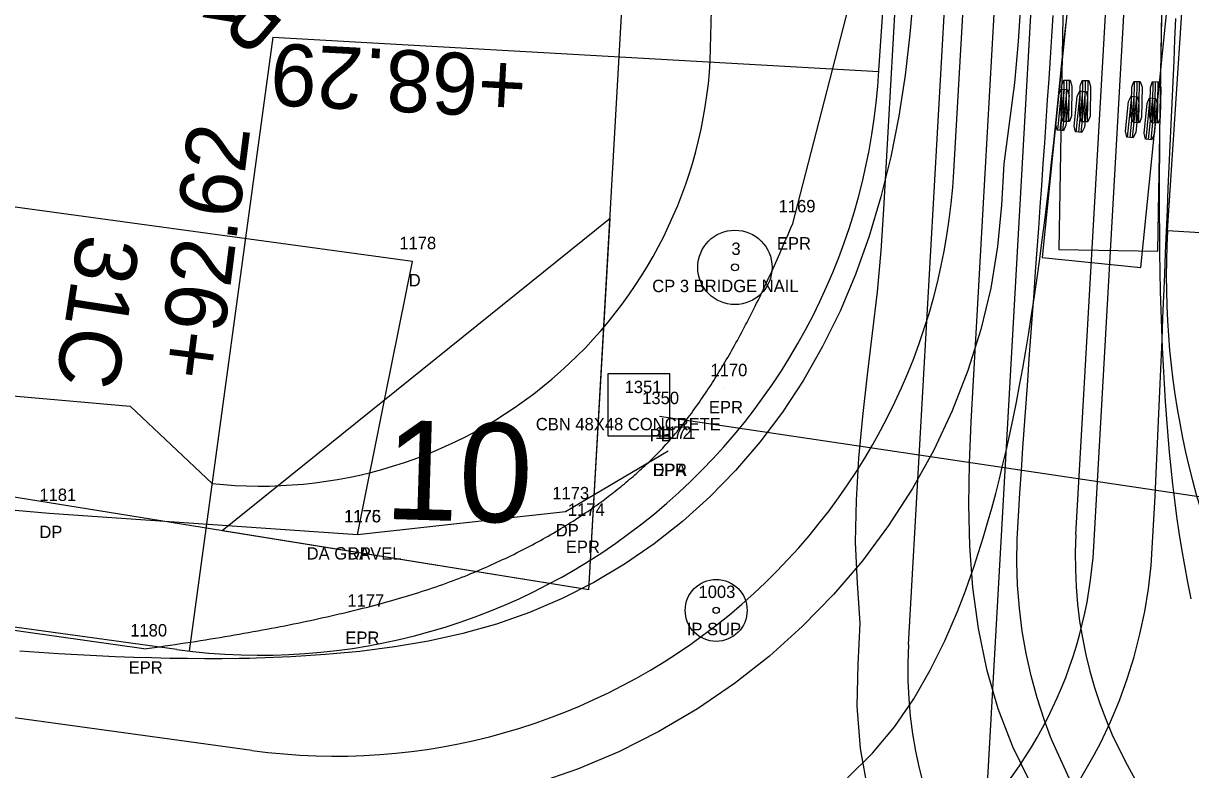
# Model space of a CAD drawing. Extents: x 1812113 to 1819860, y 1177290 to 1181185.
# Drawn here: x 1813586.4 to 1813680.6, y 1178765.6 to 1178825.8 of the extents above; entities that cross this region are included whole.
import ezdxf

# ---------------------------------------------------------------- set-up
doc = ezdxf.new("R2010")
doc.units = 0
for name, color, linetype in [('RD_EX_DR_Inlet', 7, 'Continuous'), ('RD_EX_DR_Inlet_txCode', 7, 'Continuous'), ('RD_EX_DR_Pipe', 7, 'Continuous'), ('RD_EX_DR_Pipe_txCode', 7, 'Continuous'), ('RD_EX_Driveway', 7, 'Continuous'), ('RD_EX_Driveway_txCode', 7, 'Continuous'), ('RD_EX_DV_Prop_txCode', 7, 'Continuous'), ('RD_EX_DV_PropPin', 7, 'Continuous'), ('RD_EX_Road', 7, 'Continuous'), ('RD_EX_Road_txCode', 7, 'Continuous'), ('RD_EX_RW', 7, 'Continuous'), ('RD_HC_CL', 7, 'Continuous'), ('RD_HC_Data', 7, 'Continuous'), ('RD_HC_TX_StaOther', 7, 'Continuous'), ('RD_HC_txCode', 7, 'Continuous'), ('RD_PD_ALT1_TrvlWay', 7, 'Continuous'), ('RD_PD_ALT3_TnTmp', 7, 'Continuous'), ('RD_PD_CstnLmt', 7, 'Continuous'), ('RD_PD_Final_TnTmp', 7, 'Continuous'), ('RD_PD_RW', 7, 'Continuous'), ('RD_Sketch5', 7, 'Continuous'), ('RD_Sketch7', 7, 'Continuous'), ('RD_Sketch8', 7, 'Continuous'), ('RD_Sketch9', 7, 'Continuous'), ('RD_SMD_Locator', 7, 'Continuous')]:
    doc.layers.add(name, color=color, linetype=linetype)

msp = doc.modelspace()

# ---------------------------------------------------------------- linework, layer by layer
at = {"layer": 'RD_EX_DR_Inlet'}
msp.add_line((1813638.558, 1178792.486), (1813638.558, 1178797.486), dxfattribs=at)
msp.add_lwpolyline([(1813638.558, 1178792.486), (1813638.558, 1178797.486), (1813633.558, 1178797.486), (1813633.558, 1178792.486)], close=True, dxfattribs=at)
at = {"layer": 'RD_EX_DR_Pipe'}
msp.add_line((1813690.767, 1178786.154), (1813637.713, 1178794.056), dxfattribs=at)
at = {"layer": 'RD_EX_Driveway'}
for points in [[(1813615.604, 1178795.765), (1813617.78, 1178806.553), (1813543.166, 1178816.742), (1813525.312, 1178791.789)], [(1813613.335, 1178784.516), (1813615.604, 1178795.765)], [(1813638.425, 1178791.252), (1813630.129, 1178786.377), (1813613.335, 1178784.516), (1813588.431, 1178786.243), (1813525.312, 1178791.789), (1813522.622, 1178785.744)]]:
    msp.add_lwpolyline(points, dxfattribs=at)
at = {"layer": 'RD_EX_DV_PropPin'}
for radius in [2.499, 0.25]:
    msp.add_circle((1813642.298, 1178778.414), radius, dxfattribs=at)
at = {"layer": 'RD_EX_Road'}
for p, q in [((1813653.668, 1178829.816), (1813648.43, 1178809.526)), ((1813596.091, 1178775.309), (1813522.622, 1178785.744))]:
    msp.add_line(p, q, dxfattribs=at)
msp.add_open_spline([(1813596.091, 1178775.309), (1813613.586, 1178777.713), (1813631.387, 1178785.043), (1813642.941, 1178796.308), (1813648.43, 1178809.526)], degree=2, dxfattribs=at)
at = {"layer": 'RD_EX_RW'}
for q in [(1813647.583, 1179054.502), (1813400.468, 1178817.382)]:
    msp.add_line((1813632.03, 1178780.068), q, dxfattribs=at)
at = {"layer": 'RD_HC_CL'}
msp.add_line((1813663.556, 1178753.116), (1813680.53, 1179052.635), dxfattribs=at)
at = {"layer": 'RD_HC_Data'}
for radius in [3, 0.282]:
    msp.add_circle((1813643.813, 1178806.089), radius, dxfattribs=at)
at = {"layer": 'RD_PD_ALT1_TrvlWay'}
for p, q in [((1813655.439, 1178821.971), (1813662.128, 1178921.747)), ((1813678.744, 1178809.043), (1813685.223, 1178908.833)), ((1813598.749, 1178775.26), (1813539.844, 1178783.309))]:
    msp.add_line(p, q, dxfattribs=at)
for centre, radius, start, end in [((1813605.519, 1178824.8), 50, 262.2191, 356.75649), ((1813743.64, 1178805.365), 65, 176.75649, 243.60449)]:
    msp.add_arc(centre, radius, start, end, dxfattribs=at)
at = {"layer": 'RD_PD_CstnLmt'}
for p, q in [((1813641.818, 1178822.743), (1813642.544, 1178854.467)), ((1813545.131, 1178799.286), (1813594.994, 1178794.879)), ((1813594.994, 1178794.879), (1813601.592, 1178788.655))]:
    msp.add_line(p, q, dxfattribs=at)
msp.add_arc((1813605.519, 1178824.8), 36.358, 263.80014, 356.75649, dxfattribs=at)
at = {"layer": 'RD_PD_Final_TnTmp'}
for p, q in [((1813606.513, 1178824.664), (1813599.745, 1178775.134)), ((1813606.513, 1178824.664), (1813655.433, 1178821.892)), ((1813740.735, 1178805.018), (1813678.744, 1178809.043))]:
    msp.add_line(p, q, dxfattribs=at)
at = {"layer": 'RD_PD_RW'}
for p, q in [((1813633.728, 1178810.02), (1813602.412, 1178784.841)), ((1813632.03, 1178780.068), (1813633.728, 1178810.02)), ((1813632.03, 1178780.068), (1813602.412, 1178784.841))]:
    msp.add_line(p, q, dxfattribs=at)
at = {"layer": 'RD_Sketch5'}
for p, q in [((1813672.244, 1178842.513), (1813668.622, 1178806.897)), ((1813676.581, 1178806.088), (1813680.203, 1178841.704)), ((1813672.794, 1178783.581), (1813675.97, 1178839.621)), ((1813669.875, 1178817.156), (1813670.212, 1178820.472)), ((1813670.082, 1178817.135), (1813670.419, 1178820.451)), ((1813670.289, 1178817.114), (1813670.627, 1178820.43)), ((1813671.367, 1178817.004), (1813671.704, 1178820.32)), ((1813671.574, 1178816.983), (1813671.912, 1178820.299)), ((1813671.782, 1178816.962), (1813672.119, 1178820.278)), ((1813675.512, 1178816.583), (1813675.85, 1178819.899)), ((1813675.72, 1178816.562), (1813676.057, 1178819.878)), ((1813675.927, 1178816.541), (1813676.264, 1178819.857)), ((1813677.005, 1178816.431), (1813677.342, 1178819.747)), ((1813677.212, 1178816.41), (1813677.549, 1178819.726)), ((1813677.419, 1178816.389), (1813677.756, 1178819.705)), ((1813668.622, 1178806.897), (1813676.581, 1178806.088))]:
    msp.add_line(p, q, dxfattribs=at)
for points in [[(1813662.421, 1178779.989), (1813662.682, 1178780.703), (1813663.098, 1178781.895), (1813663.491, 1178783.086), (1813663.863, 1178784.277), (1813664.215, 1178785.467), (1813664.549, 1178786.655), (1813664.867, 1178787.842), (1813665.169, 1178789.027), (1813665.456, 1178790.211), (1813665.731, 1178791.397), (1813666.003, 1178792.625), (1813666.272, 1178793.899), (1813666.536, 1178795.214), (1813666.796, 1178796.566), (1813667.05, 1178797.95), (1813667.297, 1178799.365), (1813667.537, 1178800.805), (1813667.77, 1178802.269), (1813667.995, 1178803.754), (1813668.214, 1178805.257), (1813668.425, 1178806.778), (1813668.63, 1178808.312), (1813668.828, 1178809.861), (1813669.019, 1178811.42), (1813669.204, 1178812.991), (1813669.383, 1178814.571), (1813669.557, 1178816.159), (1813669.725, 1178817.755), (1813669.889, 1178819.357), (1813670.053, 1178820.965), (1813670.217, 1178822.578), (1813670.381, 1178824.196), (1813670.546, 1178825.817)], [(1813672.832, 1178766.756), (1813673.347, 1178767.745), (1813674.143, 1178769.427), (1813674.859, 1178771.146), (1813675.495, 1178772.899), (1813676.048, 1178774.682), (1813676.517, 1178776.49), (1813676.901, 1178778.32), (1813677.198, 1178780.168), (1813677.408, 1178782.029), (1813677.536, 1178783.898), (1813677.641, 1178785.76), (1813677.738, 1178787.609), (1813677.829, 1178789.446), (1813677.914, 1178791.271), (1813677.995, 1178793.085), (1813678.073, 1178794.889), (1813678.149, 1178796.683), (1813678.223, 1178798.467), (1813678.296, 1178800.242), (1813678.368, 1178802.009), (1813678.44, 1178803.769), (1813678.512, 1178805.522), (1813678.584, 1178807.268), (1813678.657, 1178809.007), (1813678.73, 1178810.742), (1813678.804, 1178812.471), (1813678.879, 1178814.195), (1813678.954, 1178815.915), (1813679.031, 1178817.631), (1813679.108, 1178819.343), (1813679.186, 1178821.052), (1813679.265, 1178822.757), (1813679.345, 1178824.46), (1813679.426, 1178826.16)], [(1813652.907, 1178764.912), (1813654.933, 1178766.905), (1813656.713, 1178769.038), (1813658.25, 1178771.284), (1813659.584, 1178773.598), (1813660.749, 1178775.95), (1813661.774, 1178778.322), (1813662.421, 1178779.989)], [(1813671.527, 1178764.509), (1813672.832, 1178766.756)]]:
    msp.add_lwpolyline(points, dxfattribs=at)
for points in [[(1813670.341, 1178817.109), (1813669.823, 1178817.161), (1813669.715, 1178817.641), (1813669.958, 1178820.029), (1813670.161, 1178820.477), (1813670.678, 1178820.425), (1813670.787, 1178819.945), (1813670.544, 1178817.557)], [(1813671.833, 1178816.957), (1813671.316, 1178817.009), (1813671.207, 1178817.49), (1813671.45, 1178819.877), (1813671.653, 1178820.326), (1813672.17, 1178820.273), (1813672.279, 1178819.793), (1813672.036, 1178817.405)], [(1813675.978, 1178816.535), (1813675.461, 1178816.588), (1813675.352, 1178817.068), (1813675.595, 1178819.456), (1813675.798, 1178819.904), (1813676.316, 1178819.852), (1813676.424, 1178819.372), (1813676.181, 1178816.984)], [(1813677.471, 1178816.384), (1813676.953, 1178816.436), (1813676.845, 1178816.916), (1813677.087, 1178819.304), (1813677.291, 1178819.753), (1813677.808, 1178819.7), (1813677.917, 1178819.22), (1813677.674, 1178816.832)]]:
    msp.add_lwpolyline(points, close=True, dxfattribs=at)
msp.add_arc((1813637.85, 1178785.561), 35, 262.2191, 356.75649, dxfattribs=at)
at = {"layer": 'RD_Sketch7'}
for p, q in [((1813670.575, 1178843.323), (1813669.969, 1178807.528)), ((1813677.968, 1178807.393), (1813678.574, 1178843.188)), ((1813671.346, 1178784.53), (1813674.532, 1178840.756)), ((1813670.352, 1178817.857), (1813670.409, 1178821.189)), ((1813670.56, 1178817.853), (1813670.617, 1178821.186)), ((1813670.769, 1178817.85), (1813670.825, 1178821.182)), ((1813671.852, 1178817.831), (1813671.908, 1178821.164)), ((1813672.06, 1178817.828), (1813672.117, 1178821.161)), ((1813672.268, 1178817.824), (1813672.325, 1178821.157)), ((1813676.018, 1178817.761), (1813676.074, 1178821.094)), ((1813676.226, 1178817.757), (1813676.283, 1178821.09)), ((1813676.435, 1178817.754), (1813676.491, 1178821.086)), ((1813677.518, 1178817.735), (1813677.574, 1178821.068)), ((1813677.726, 1178817.732), (1813677.782, 1178821.065)), ((1813677.934, 1178817.728), (1813677.991, 1178821.061)), ((1813669.969, 1178807.528), (1813677.968, 1178807.393))]:
    msp.add_line(p, q, dxfattribs=at)
for points in [[(1813680.661, 1178779.355), (1813680.381, 1178780.702), (1813680.127, 1178782.04), (1813679.896, 1178783.37), (1813679.687, 1178784.691), (1813679.498, 1178786.003), (1813679.326, 1178787.307), (1813679.17, 1178788.603), (1813679.03, 1178789.891), (1813678.903, 1178791.18), (1813678.785, 1178792.506), (1813678.675, 1178793.87), (1813678.576, 1178795.268), (1813678.486, 1178796.696), (1813678.407, 1178798.15), (1813678.337, 1178799.628), (1813678.277, 1178801.128), (1813678.226, 1178802.645), (1813678.185, 1178804.179), (1813678.152, 1178805.728), (1813678.128, 1178807.29), (1813678.111, 1178808.863), (1813678.102, 1178810.446), (1813678.1, 1178812.039), (1813678.105, 1178813.639), (1813678.116, 1178815.247), (1813678.133, 1178816.861), (1813678.156, 1178818.481), (1813678.183, 1178820.106), (1813678.211, 1178821.736), (1813678.238, 1178823.37), (1813678.266, 1178825.007), (1813678.294, 1178826.648)], [(1813669.281, 1178768.228), (1813668.772, 1178769.603), (1813668.207, 1178771.351), (1813667.723, 1178773.128), (1813667.323, 1178774.93), (1813667.007, 1178776.753), (1813666.777, 1178778.592), (1813666.633, 1178780.444), (1813666.576, 1178782.303), (1813666.607, 1178784.166), (1813666.711, 1178786.025), (1813666.827, 1178787.872), (1813666.948, 1178789.705), (1813667.072, 1178791.527), (1813667.198, 1178793.338), (1813667.325, 1178795.138), (1813667.453, 1178796.929), (1813667.582, 1178798.71), (1813667.71, 1178800.483), (1813667.838, 1178802.248), (1813667.966, 1178804.005), (1813668.092, 1178805.756), (1813668.217, 1178807.501), (1813668.341, 1178809.24), (1813668.464, 1178810.973), (1813668.585, 1178812.702), (1813668.706, 1178814.427), (1813668.824, 1178816.147), (1813668.942, 1178817.864), (1813669.058, 1178819.577), (1813669.173, 1178821.287), (1813669.287, 1178822.994), (1813669.399, 1178824.699), (1813669.511, 1178826.401)], [(1813670.936, 1178764.574), (1813669.416, 1178767.888), (1813669.281, 1178768.228)]]:
    msp.add_lwpolyline(points, dxfattribs=at)
for points in [[(1813670.82, 1178817.849), (1813670.3, 1178817.857), (1813670.152, 1178818.327), (1813670.192, 1178820.726), (1813670.357, 1178821.19), (1813670.877, 1178821.182), (1813671.026, 1178820.712), (1813670.985, 1178818.313)], [(1813672.32, 1178817.823), (1813671.8, 1178817.832), (1813671.651, 1178818.301), (1813671.692, 1178820.701), (1813671.857, 1178821.165), (1813672.377, 1178821.156), (1813672.525, 1178820.687), (1813672.485, 1178818.287)], [(1813676.486, 1178817.753), (1813675.966, 1178817.762), (1813675.818, 1178818.231), (1813675.858, 1178820.63), (1813676.023, 1178821.094), (1813676.543, 1178821.086), (1813676.691, 1178820.616), (1813676.651, 1178818.217)], [(1813677.986, 1178817.727), (1813677.466, 1178817.736), (1813677.317, 1178818.205), (1813677.358, 1178820.605), (1813677.523, 1178821.069), (1813678.042, 1178821.06), (1813678.191, 1178820.591), (1813678.151, 1178818.191)]]:
    msp.add_lwpolyline(points, close=True, dxfattribs=at)
msp.add_arc((1813706.29, 1178782.549), 35, 176.75649, 248.72202, dxfattribs=at)
at = {"layer": 'RD_Sketch8'}
msp.add_line((1813657.822, 1178775.655), (1813662.021, 1178849.759), dxfattribs=at)
for points in [[(1813656.751, 1178827.461), (1813656.562, 1178824.123), (1813656.373, 1178820.785), (1813656.184, 1178817.447), (1813655.995, 1178814.109), (1813655.806, 1178810.771), (1813655.596, 1178807.434), (1813655.292, 1178804.102), (1813654.904, 1178800.769), (1813654.494, 1178797.425), (1813654.113, 1178794.065), (1813653.803, 1178790.685), (1813653.599, 1178787.295), (1813653.528, 1178783.917), (1813653.679, 1178780.611), (1813653.9, 1178777.386), (1813653.725, 1178774.053), (1813653.648, 1178770.684), (1813653.917, 1178767.267), (1813654.533, 1178763.843)], [(1813664.739, 1178827.009), (1813664.549, 1178823.671), (1813664.36, 1178820.333), (1813664.171, 1178816.995), (1813663.982, 1178813.657), (1813663.793, 1178810.319), (1813663.604, 1178806.981), (1813663.414, 1178803.643), (1813663.225, 1178800.305), (1813663.036, 1178796.967), (1813662.854, 1178793.628), (1813662.718, 1178790.288), (1813662.671, 1178786.945), (1813662.753, 1178783.603), (1813663.001, 1178780.27), (1813663.448, 1178776.959), (1813664.123, 1178773.687), (1813665.048, 1178770.49), (1813666.214, 1178767.448), (1813667.612, 1178764.595)]]:
    msp.add_lwpolyline(points, dxfattribs=at)
msp.add_arc((1813692.766, 1178773.675), 35, 176.75649, 250.88672, dxfattribs=at)
at = {"layer": 'RD_Sketch9'}
for p, q in [((1813661.488, 1178813.827), (1813662.81, 1178837.155)), ((1813604.798, 1178767.116), (1813538.862, 1178776.126))]:
    msp.add_line(p, q, dxfattribs=at)
for points in [[(1813658.241, 1178828.224), (1813657.939, 1178824.9), (1813657.545, 1178821.585), (1813657.037, 1178818.287), (1813656.397, 1178815.012), (1813655.607, 1178811.77), (1813654.66, 1178808.592), (1813653.558, 1178805.514), (1813652.302, 1178802.548), (1813650.896, 1178799.705), (1813649.342, 1178796.992), (1813647.646, 1178794.416), (1813645.815, 1178791.983), (1813643.856, 1178789.698), (1813641.776, 1178787.566), (1813639.583, 1178785.592), (1813637.285, 1178783.781), (1813634.892, 1178782.137), (1813632.413, 1178780.664), (1813629.857, 1178779.365), (1813627.235, 1178778.244), (1813624.557, 1178777.303), (1813621.835, 1178776.541), (1813619.083, 1178775.937), (1813616.313, 1178775.466), (1813613.534, 1178775.108), (1813610.751, 1178774.847), (1813607.966, 1178774.668), (1813605.183, 1178774.561), (1813604.626, 1178774.547)], [(1813666.885, 1178827.677), (1813666.688, 1178824.319), (1813666.398, 1178820.98), (1813665.95, 1178817.698), (1813665.529, 1178814.437), (1813665.34, 1178811.105), (1813665.026, 1178807.76), (1813664.466, 1178804.408), (1813663.665, 1178801.071), (1813662.627, 1178797.769), (1813661.358, 1178794.519), (1813659.863, 1178791.343), (1813658.15, 1178788.256), (1813656.226, 1178785.276), (1813654.1, 1178782.418), (1813651.78, 1178779.699), (1813649.278, 1178777.132), (1813646.604, 1178774.73), (1813643.77, 1178772.506), (1813640.79, 1178770.471), (1813637.676, 1178768.636), (1813634.442, 1178767.009), (1813631.103, 1178765.599), (1813627.675, 1178764.412)], [(1813604.626, 1178774.547), (1813603.791, 1178774.53), (1813602.401, 1178774.515), (1813601.011, 1178774.512), (1813599.616, 1178774.522), (1813598.192, 1178774.544), (1813596.743, 1178774.577), (1813595.271, 1178774.623), (1813593.778, 1178774.68), (1813592.267, 1178774.748), (1813590.741, 1178774.826), (1813589.2, 1178774.914), (1813587.647, 1178775.012), (1813586.083, 1178775.118)]]:
    msp.add_lwpolyline(points, dxfattribs=at)
msp.add_arc((1813611.568, 1178816.656), 50, 262.2191, 356.75649, dxfattribs=at)
at = {"layer": 'RD_SMD_Locator'}
for centre in [(1813648.43, 1178809.526), (1813617.78, 1178806.553), (1813643.813, 1178806.089), (1813642.941, 1178796.308), (1813637.713, 1178794.056), (1813638.425, 1178791.252), (1813638.425, 1178791.252), (1813588.431, 1178786.243), (1813630.129, 1178786.377), (1813613.335, 1178784.516), (1813613.335, 1178784.516), (1813631.387, 1178785.043), (1813613.586, 1178777.713), (1813596.091, 1178775.309)]:
    msp.add_circle(centre, 0.001, dxfattribs=at)

# ---------------------------------------------------------------- texts
at = {"layer": 'RD_EX_DR_Inlet_txCode'}
for s, p in [('1351', (1813634.905, 1178795.941)), ('CBN 48X48 CONCRETE', (1813627.736, 1178792.941))]:
    msp.add_text(s, height=1, dxfattribs=at).set_placement(p)
at = {"layer": 'RD_EX_DR_Pipe_txCode'}
for s, p in [('1350', (1813636.327, 1178795.056)), ('PB', (1813636.933, 1178792.056))]:
    msp.add_text(s, height=1, dxfattribs=at).set_placement(p)
at = {"layer": 'RD_EX_Driveway_txCode'}
for s, p in [('1178', (1813616.717, 1178807.553)), ('D', (1813617.473, 1178804.553)), ('1172', (1813637.362, 1178792.252)), ('DPA', (1813637.157, 1178789.252)), ('1181', (1813587.651, 1178787.243)), ('1173', (1813629.066, 1178787.377)), ('1176', (1813612.248, 1178785.516)), ('1175', (1813612.272, 1178785.516)), ('DP', (1813587.651, 1178784.243)), ('DP', (1813629.35, 1178784.377)), ('DA GRAVEL', (1813609.233, 1178782.516)), ('DP', (1813612.555, 1178782.516))]:
    msp.add_text(s, height=1, dxfattribs=at).set_placement(p)
at = {"layer": 'RD_EX_DV_Prop_txCode'}
for s, p in [('1003', (1813640.873, 1178779.414)), ('IP SUP', (1813639.928, 1178776.414))]:
    msp.add_text(s, height=1, dxfattribs=at).set_placement(p)
at = {"layer": 'RD_EX_Road_txCode'}
for s, p in [('1169', (1813647.343, 1178810.526)), ('EPR', (1813647.201, 1178807.526)), ('1170', (1813641.839, 1178797.308)), ('EPR', (1813641.713, 1178794.308)), ('1171', (1813637.645, 1178792.252)), ('EPR', (1813637.196, 1178789.252)), ('1174', (1813630.324, 1178786.043)), ('EPR', (1813630.158, 1178783.043)), ('1177', (1813612.523, 1178778.713)), ('1180', (1813594.989, 1178776.309)), ('EPR', (1813612.357, 1178775.713)), ('EPR', (1813594.863, 1178773.309))]:
    msp.add_text(s, height=1, dxfattribs=at).set_placement(p)
at = {"layer": 'RD_HC_TX_StaOther'}
msp.add_text('10', height=8, rotation=358.26941, dxfattribs=at).set_placement((1813615.465, 1178785.804))
at = {"layer": 'RD_HC_txCode'}
for s, p in [('3', (1813643.53, 1178807.089)), ('CP 3 BRIDGE NAIL', (1813637.136, 1178804.089))]:
    msp.add_text(s, height=1, dxfattribs=at).set_placement(p)
at = {"layer": 'RD_PD_ALT3_TnTmp'}
for s, rotation, p in [("50'R", 229.38478, (1813609.408, 1178836.329)), ('+68.29', 177.03208, (1813627.091, 1178823.106)), ('+92.62', 82.76259, (1813602.095, 1178796.804))]:
    msp.add_text(s, height=5, rotation=rotation, dxfattribs=at).set_placement(p)
at = {"layer": 'RD_PD_CstnLmt'}
msp.add_text('31C', height=5, rotation=261.16162, dxfattribs=at).set_placement((1813590.834, 1178808.904))

doc.saveas('drawing.dxf')
